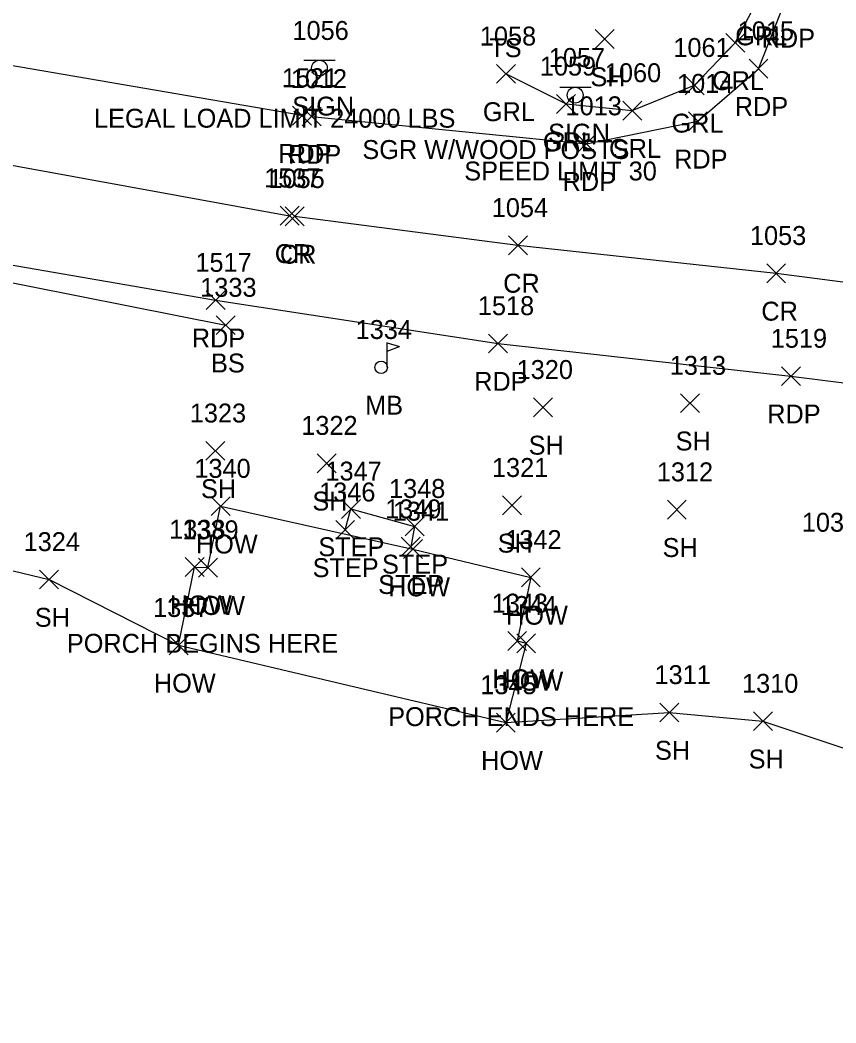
# Model space of a CAD drawing. Extents: x 1616726 to 1619875, y 273782 to 276557.
# Drawn here: x 1616958.6 to 1617044.9, y 276105.3 to 276211.4 of the extents above; entities that cross this region are included whole.
import ezdxf

# ---------------------------------------------------------------- set-up
doc = ezdxf.new("R2010")
doc.units = 0
for name, color, linetype in [('L_A', 7, 'Continuous'), ('L_C', 7, 'Continuous'), ('L_I', 7, 'Continuous'), ('L_TIC', 7, 'Continuous'), ('LBC', 7, 'Continuous'), ('LBF', 7, 'Continuous'), ('LELB', 7, 'Continuous'), ('LMB', 7, 'Continuous'), ('LSOGP', 7, 'Continuous'), ('P_A', 7, 'Continuous'), ('P_I', 7, 'Continuous'), ('P_TIC', 7, 'Continuous'), ('PET', 7, 'Continuous'), ('PRC', 7, 'Continuous'), ('R_A', 7, 'Continuous'), ('R_C', 7, 'Continuous'), ('R_I', 7, 'Continuous'), ('R_TIC', 7, 'Continuous'), ('RGR', 7, 'Continuous'), ('S_A', 7, 'Continuous'), ('S_C', 7, 'Continuous'), ('S_I', 7, 'Continuous'), ('SSGN', 7, 'Continuous')]:
    doc.layers.add(name, color=color, linetype=linetype)

msp = doc.modelspace()

# ---------------------------------------------------------------- linework, layer by layer
at = {"layer": 'L_TIC'}
for points in [[(1617019.41, 276208.38), (1617021.41, 276210.38)], [(1617021.41, 276208.38), (1617019.41, 276210.38)], [(1616979.35, 276178.12), (1616981.35, 276180.12)], [(1616981.35, 276178.12), (1616979.35, 276180.12)], [(1617028.42, 276169.87), (1617030.42, 276171.87)], [(1617030.42, 276169.87), (1617028.42, 276171.87)], [(1617012.88, 276169.43), (1617014.88, 276171.43)], [(1617014.88, 276169.43), (1617012.88, 276171.43)], [(1616978.25, 276164.83), (1616980.25, 276166.83)], [(1616980.25, 276164.83), (1616978.25, 276166.83)], [(1616990.02, 276163.52), (1616992.02, 276165.52)], [(1616992.02, 276163.52), (1616990.02, 276165.52)], [(1617009.61, 276159.07), (1617011.61, 276161.07)], [(1617011.61, 276159.07), (1617009.61, 276161.07)], [(1616978.81, 276158.98), (1616980.81, 276160.98)], [(1616980.81, 276158.98), (1616978.81, 276160.98)], [(1616992.58, 276158.69), (1616994.58, 276160.69)], [(1616994.58, 276158.69), (1616992.58, 276160.69)], [(1617027.04, 276158.61), (1617029.04, 276160.61)], [(1617029.04, 276158.61), (1617027.04, 276160.61)], [(1616991.97, 276156.48), (1616993.97, 276158.48)], [(1616993.97, 276156.48), (1616991.97, 276158.48)], [(1616999.31, 276156.85), (1617001.31, 276158.85)], [(1617001.31, 276156.85), (1616999.31, 276158.85)], [(1616998.9, 276154.7), (1617000.9, 276156.7)], [(1617000.9, 276154.7), (1616998.9, 276156.7)], [(1616999.14, 276154.45), (1617001.14, 276156.45)], [(1617001.14, 276154.45), (1616999.14, 276156.45)], [(1616976.06, 276152.54), (1616978.06, 276154.54)], [(1616978.06, 276152.54), (1616976.06, 276154.54)], [(1616977.46, 276152.48), (1616979.46, 276154.48)], [(1616979.46, 276152.48), (1616977.46, 276154.48)], [(1616960.67, 276151.23), (1616962.67, 276153.23)], [(1616962.67, 276151.23), (1616960.67, 276153.23)], [(1617011.6, 276151.45), (1617013.6, 276153.45)], [(1617013.6, 276151.45), (1617011.6, 276153.45)], [(1616974.36, 276144.27), (1616976.36, 276146.27)], [(1616976.36, 276144.27), (1616974.36, 276146.27)], [(1617010.16, 276144.73), (1617012.16, 276146.73)], [(1617012.16, 276144.73), (1617010.16, 276146.73)], [(1617011.11, 276144.48), (1617013.11, 276146.48)], [(1617013.11, 276144.48), (1617011.11, 276146.48)], [(1617026.24, 276137.17), (1617028.24, 276139.17)], [(1617028.24, 276137.17), (1617026.24, 276139.17)], [(1617008.96, 276136.1), (1617010.96, 276138.1)], [(1617010.96, 276136.1), (1617008.96, 276138.1)], [(1617036.14, 276136.25), (1617038.14, 276138.25)], [(1617038.14, 276136.25), (1617036.14, 276138.25)]]:
    msp.add_lwpolyline(points, dxfattribs=at)
at = {"layer": 'LBC'}
msp.add_lwpolyline([(1616975.36, 276145.27), (1616977.06, 276153.54), (1616978.46, 276153.48), (1616979.81, 276159.98), (1617000.14, 276155.45), (1617012.6, 276152.45), (1617011.16, 276145.73), (1617012.11, 276145.48), (1617009.96, 276137.1)], dxfattribs=at)
at = {"layer": 'LBF'}
msp.add_lwpolyline([(1616992.97, 276157.48), (1616993.58, 276159.69), (1617000.31, 276157.85), (1616999.9, 276155.7)], dxfattribs=at)
at = {"layer": 'LELB'}
msp.add_lwpolyline([(1616903.79, 276194.77), (1616916.44, 276191.78), (1616933.37, 276188.22), (1616954.41, 276184.27), (1616980.35, 276179.12)], dxfattribs=at)
at = {"layer": 'LMB'}
for p, q in [((1616997.43, 276174.67), (1616997.43, 276177.27)), ((1616997.43, 276177.26), (1616998.72, 276176.88)), ((1616997.43, 276176.36), (1616998.72, 276176.87)), ((1616996.78, 276174.66), (1616996.78, 276174.66))]:
    msp.add_line(p, q, dxfattribs=at)
msp.add_circle((1616996.78, 276174.66), 0.656, dxfattribs=at)
at = {"layer": 'LSOGP'}
msp.add_lwpolyline([(1616868.68, 276170.68), (1616889.93, 276166.26), (1616914.47, 276162.37), (1616938.21, 276157.87), (1616961.67, 276152.23), (1616975.36, 276145.27), (1617009.96, 276137.1), (1617027.24, 276138.17), (1617037.14, 276137.25), (1617054.32, 276131.49), (1617066.36, 276127.08), (1617078.89, 276126), (1617091.1, 276125.93), (1617113.14, 276115.76), (1617128.25, 276113.28), (1617136.7, 276109.65), (1617140.03, 276109.3), (1617154.79, 276105.34)], dxfattribs=at)
at = {"layer": 'P_TIC'}
for points in [[(1617035.67, 276205.24), (1617037.67, 276207.24)], [(1617037.67, 276205.24), (1617035.67, 276207.24)], [(1616987.41, 276200.28), (1616989.41, 276202.28)], [(1616989.41, 276200.28), (1616987.41, 276202.28)], [(1616988.43, 276200.18), (1616990.43, 276202.18)], [(1616990.43, 276200.18), (1616988.43, 276202.18)], [(1617029.26, 276199.68), (1617031.26, 276201.68)], [(1617031.26, 276199.68), (1617029.26, 276201.68)], [(1617017.47, 276197.31), (1617019.47, 276199.31)], [(1617019.47, 276197.31), (1617017.47, 276199.31)], [(1616986.1, 276189.69), (1616988.1, 276191.69)], [(1616988.1, 276189.69), (1616986.1, 276191.69)], [(1616986.63, 276189.62), (1616988.63, 276191.62)], [(1616988.63, 276189.62), (1616986.63, 276191.62)], [(1617010.24, 276186.55), (1617012.24, 276188.55)], [(1617012.24, 276186.55), (1617010.24, 276188.55)], [(1617037.54, 276183.6), (1617039.54, 276185.6)], [(1617039.54, 276183.6), (1617037.54, 276185.6)], [(1616978.27, 276180.76), (1616980.27, 276182.76)], [(1616980.27, 276180.76), (1616978.27, 276182.76)], [(1617008.13, 276176.18), (1617010.13, 276178.18)], [(1617010.13, 276176.18), (1617008.13, 276178.18)], [(1617039.1, 276172.73), (1617041.1, 276174.73)], [(1617041.1, 276172.73), (1617039.1, 276174.73)]]:
    msp.add_lwpolyline(points, dxfattribs=at)
at = {"layer": 'PET'}
for points in [[(1616988.41, 276201.28), (1616954.9, 276207.04), (1616922.49, 276213.04), (1616897.19, 276219.39), (1616868.83, 276227.99), (1616843.51, 276236.97), (1616821.5, 276246.17), (1616797.48, 276256.89), (1616777.93, 276266.16)], [(1616769.24, 276246.91), (1616790.9, 276236.62), (1616808.6, 276228.19), (1616836.41, 276217.31), (1616861.69, 276208.81), (1616891.18, 276199.57), (1616916.28, 276193.27), (1616944.97, 276187.68), (1616979.27, 276181.76), (1617009.13, 276177.18), (1617040.1, 276173.73), (1617058.02, 276171.48)], [(1616989.43, 276201.18), (1617018.47, 276198.31), (1617030.26, 276200.68), (1617036.67, 276206.24), (1617039.51, 276213.46), (1617039.81, 276219.44), (1617036.61, 276227.11), (1617032.44, 276230.39), (1617046.65, 276234.32), (1617061.09, 276238.88), (1617067.9, 276234.23), (1617072.4, 276230.99), (1617088.6, 276220.19), (1617112.48, 276205), (1617131.16, 276194.64), (1617156.36, 276182.31), (1617186.3, 276169.87), (1617215.5, 276159.97), (1617247.44, 276151.44), (1617259.73, 276148.35), (1617264.1, 276152.29), (1617286.33, 276147.09), (1617304.44, 276145.41), (1617352.2, 276136.04)]]:
    msp.add_lwpolyline(points, dxfattribs=at)
at = {"layer": 'PRC'}
for points in [[(1616773.7, 276256.44), (1616798, 276244.91), (1616831.43, 276231.02), (1616858.04, 276221.16), (1616889.3, 276211.07), (1616917.92, 276203.82), (1616952.65, 276196.97), (1616987.1, 276190.69)], [(1617099.13, 276175.38), (1617067.78, 276180.77), (1617038.54, 276184.6), (1617011.24, 276187.55), (1616987.63, 276190.62)]]:
    msp.add_lwpolyline(points, dxfattribs=at)
at = {"layer": 'R_TIC'}
for points in [[(1617033.21, 276207.97), (1617035.21, 276209.97)], [(1617035.21, 276207.97), (1617033.21, 276209.97)], [(1617008.98, 276204.69), (1617010.98, 276206.69)], [(1617010.98, 276204.69), (1617008.98, 276206.69)], [(1617028.92, 276203.48), (1617030.92, 276205.48)], [(1617030.92, 276203.48), (1617028.92, 276205.48)], [(1617015.33, 276201.51), (1617017.33, 276203.51)], [(1617017.33, 276201.51), (1617015.33, 276203.51)], [(1617022.33, 276200.81), (1617024.33, 276202.81)], [(1617024.33, 276200.81), (1617022.33, 276202.81)]]:
    msp.add_lwpolyline(points, dxfattribs=at)
at = {"layer": 'RGR'}
msp.add_lwpolyline([(1617009.98, 276205.69), (1617016.33, 276202.51), (1617023.33, 276201.81), (1617029.92, 276204.48), (1617034.21, 276208.97), (1617036.66, 276213.71), (1617037.18, 276219.21), (1617035.18, 276225.6), (1617031.93, 276229.86)], dxfattribs=at)
at = {"layer": 'SSGN'}
for p, q in [((1616988.6, 276207.13), (1616991.93, 276207.13)), ((1616990.25, 276206.3), (1616990.25, 276206.3)), ((1617015.65, 276204.27), (1617018.98, 276204.27)), ((1617017.29, 276203.44), (1617017.29, 276203.44))]:
    msp.add_line(p, q, dxfattribs=at)
for centre in [(1616990.25, 276206.3), (1617017.29, 276203.44)]:
    msp.add_circle(centre, 0.833, dxfattribs=at)

# ---------------------------------------------------------------- texts
at = {"layer": 'L_A'}
for s, p in [('TS', (1617008.21, 276207.46)), ('SH', (1617018.9, 276204.38)), ('BS', (1616978.79, 276174.12)), ('MB', (1616995.08, 276169.66)), ('SH', (1617012.37, 276165.43)), ('SH', (1617027.91, 276165.87)), ('SH', (1616977.73, 276160.83)), ('SH', (1616989.51, 276159.52)), ('HOW', (1616977.19, 276154.98)), ('SH', (1617009.1, 276155.07)), ('STEP', (1616990.14, 276154.69)), ('SH', (1617026.53, 276154.61)), ('STEP', (1616996.87, 276152.85)), ('STEP', (1616989.53, 276152.48)), ('STEP', (1616996.46, 276150.7)), ('HOW', (1616997.52, 276150.45)), ('HOW', (1616974.44, 276148.54)), ('HOW', (1616975.85, 276148.48)), ('HOW', (1617009.98, 276147.45)), ('SH', (1616960.16, 276147.23)), ('HOW', (1616972.75, 276140.27)), ('HOW', (1617008.54, 276140.73)), ('HOW', (1617009.49, 276140.48)), ('SH', (1617025.73, 276133.17)), ('HOW', (1617007.34, 276132.1)), ('SH', (1617035.63, 276132.25))]:
    msp.add_text(s, height=2, dxfattribs=at).set_placement(p)
at = {"layer": 'L_C'}
for s, p in [('PORCH BEGINS HERE', (1616963.55, 276144.48)), ('PORCH ENDS HERE', (1616997.52, 276136.73))]:
    msp.add_text(s, height=2, dxfattribs=at).set_placement(p)
at = {"layer": 'L_I'}
for s, p in [('1333', (1616977.65, 276182.12)), ('1334', (1616994.08, 276177.66)), ('1313', (1617027.29, 276173.87)), ('1320', (1617011.1, 276173.43)), ('1323', (1616976.55, 276168.83)), ('1322', (1616988.33, 276167.52)), ('1340', (1616977.03, 276162.98)), ('1347', (1616990.89, 276162.69)), ('1321', (1617008.49, 276163.07)), ('1312', (1617025.92, 276162.61)), ('1346', (1616990.22, 276160.48)), ('1348', (1616997.61, 276160.85)), ('1349', (1616997.2, 276158.7)), ('1341', (1616998.01, 276158.45)), ('1338', (1616974.37, 276156.54)), ('1339', (1616975.76, 276156.48)), ('1324', (1616958.98, 276155.23)), ('1342', (1617009.9, 276155.45)), ('1343', (1617008.46, 276148.73)), ('1344', (1617009.41, 276148.48)), ('1337', (1616972.67, 276148.27)), ('1311', (1617025.68, 276141.17)), ('1345', (1617007.26, 276140.1)), ('1310', (1617034.93, 276140.25))]:
    msp.add_text(s, height=2, dxfattribs=at).set_placement(p)
at = {"layer": 'P_A'}
for s, p in [('RDP', (1617037, 276208.46)), ('RDP', (1617034.16, 276201.24)), ('RDP', (1616985.89, 276196.28)), ('RDP', (1616986.91, 276196.18)), ('RDP', (1617027.75, 276195.68)), ('RDP', (1617015.96, 276193.31)), ('CR', (1616985.53, 276185.69)), ('CR', (1616986.07, 276185.62)), ('CR', (1617009.68, 276182.55)), ('CR', (1617036.97, 276179.6)), ('RDP', (1616976.76, 276176.76)), ('RDP', (1617006.61, 276172.18)), ('RDP', (1617037.59, 276168.73))]:
    msp.add_text(s, height=2, dxfattribs=at).set_placement(p)
at = {"layer": 'P_I'}
for s, p in [('1015', (1617034.47, 276209.24)), ('1521', (1616986.28, 276204.28)), ('1012', (1616987.22, 276204.18)), ('1014', (1617028.06, 276203.68)), ('1013', (1617016.27, 276201.31)), ('1537', (1616984.41, 276193.69)), ('1055', (1616984.86, 276193.62)), ('1054', (1617008.47, 276190.55)), ('1053', (1617035.77, 276187.6)), ('1517', (1616977.14, 276184.76)), ('1518', (1617007, 276180.18)), ('1519', (1617037.97, 276176.73))]:
    msp.add_text(s, height=2, dxfattribs=at).set_placement(p)
at = {"layer": 'R_A'}
for p in [(1617034.21, 276208.71), (1617031.75, 276203.97), (1617007.53, 276200.69), (1617027.47, 276199.48), (1617013.87, 276197.51), (1617020.87, 276196.81)]:
    msp.add_text('GRL', height=2, dxfattribs=at).set_placement(p)
at = {"layer": 'R_C'}
msp.add_text('SGR W/WOOD POSTS', height=2, dxfattribs=at).set_placement((1616994.79, 276196.69))
at = {"layer": 'R_I'}
for s, p in [('1058', (1617007.21, 276208.69)), ('1061', (1617027.67, 276207.48)), ('1059', (1617013.55, 276205.51)), ('1060', (1617020.43, 276204.81))]:
    msp.add_text(s, height=2, dxfattribs=at).set_placement(p)
at = {"layer": 'S_A'}
for p in [(1616987.38, 276201.28), (1617014.43, 276198.42)]:
    msp.add_text('SIGN', height=2, dxfattribs=at).set_placement(p)
at = {"layer": 'S_C'}
for s, p in [('LEGAL LOAD LIMIT 24000 LBS', (1616966.42, 276200)), ('SPEED LIMIT 30', (1617005.56, 276194.42)), ('1030/1407/0245', (1617041.25, 276157.28))]:
    msp.add_text(s, height=2, dxfattribs=at).set_placement(p)
at = {"layer": 'S_I'}
for s, p in [('1056', (1616987.4, 276209.28)), ('1057', (1617014.5, 276206.42))]:
    msp.add_text(s, height=2, dxfattribs=at).set_placement(p)

doc.saveas('drawing.dxf')
